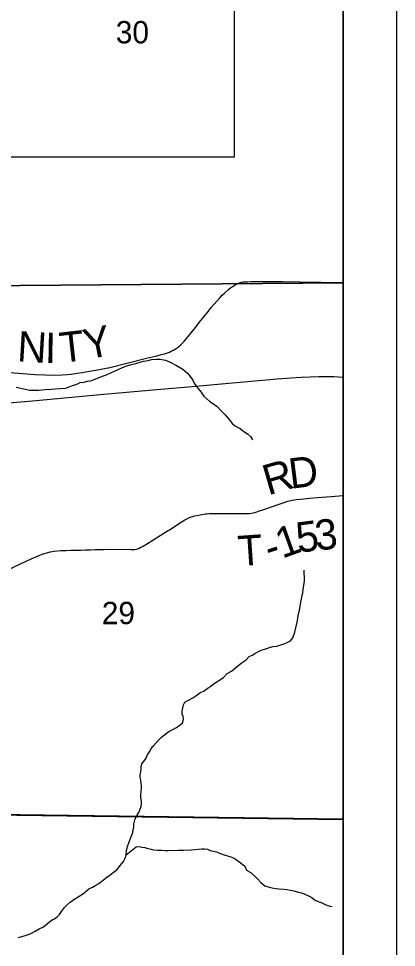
# Model space of a CAD drawing. Extents: x 0 to 34, y 0 to 22.
# Drawn here: x 16.791 to 17.5, y 16.673 to 18.414 of the extents above; entities that cross this region are included whole.
import ezdxf

# ---------------------------------------------------------------- set-up
doc = ezdxf.new("R2010")
doc.units = 0
for name, color, linetype in [('GM_X_Corporation', 7, 'Continuous'), ('GM_X_Minor_River', 7, 'Continuous'), ('GM_X_Rail_Line', 7, 'Continuous'), ('GM_X_Section_Text', 7, 'Continuous'), ('GM_X_Township_Road', 7, 'Continuous'), ('GM_X_Township_Road_Text', 7, 'Continuous'), ('SH_Data', 7, 'Continuous'), ('SH_Text', 7, 'Continuous')]:
    doc.layers.add(name, color=color, linetype=linetype)

msp = doc.modelspace()

# ---------------------------------------------------------------- linework, layer by layer
at = {"layer": 'GM_X_Corporation'}
for points in [[(17.4, 16.913), (17.4, 20.4), (16.7661, 20.4), (16.7652, 20.328), (16.7547, 19.2837), (16.7532, 19.0614), (16.752, 18.8891), (16.5475, 18.8929), (16.5174, 18.8935), (16.5168, 18.8707), (16.4886, 17.7392), (16.4807, 17.4161), (16.4704, 17.0104), (16.4703, 17.0036), (16.4689, 16.9245), (16.5516, 16.9243)], [(17.4, 17.9189), (17.4, 18.8808), (16.7485, 18.8896), (16.5138, 18.8938), (16.4906, 17.9114)], [(17.4, 16.9134), (17.4, 17.9189), (16.4906, 17.9114), (16.466, 16.9263)], [(16.4214, 13.6), (17.4, 13.6), (17.4, 16.913), (16.5516, 16.9243), (16.4689, 16.9245), (16.4603, 16.2617), (16.4611, 16.1288), (16.4516, 15.5964), (16.4498, 15.4626), (16.4419, 14.8642), (16.438, 14.5908), (16.4339, 14.3806), (16.4212, 13.6609)], [(17.4, 15.8967), (17.4, 16.9134), (16.466, 16.9263), (16.466, 16.9214), (16.4563, 15.9084)]]:
    msp.add_lwpolyline(points, close=True, dxfattribs=at)
at = {"layer": 'GM_X_Minor_River'}
for points in [[(16.7866, 17.7233), (16.7923, 17.7223), (16.8037, 17.7198), (16.8124, 17.7181), (16.8189, 17.7178), (16.8287, 17.718), (16.8412, 17.719), (16.853, 17.7199), (16.8601, 17.7204), (16.8692, 17.721), (16.8791, 17.7215), (16.8859, 17.7239), (16.8923, 17.7267), (16.899, 17.7287), (16.9066, 17.7319), (16.9141, 17.7328), (16.9198, 17.7344), (16.9258, 17.7352), (16.9349, 17.7384), (16.9405, 17.7412), (16.9507, 17.7448), (16.9571, 17.7472), (16.9654, 17.7511), (16.9778, 17.7563), (16.9864, 17.7602), (16.9944, 17.7634), (17.0008, 17.7654), (17.011, 17.7679), (17.0193, 17.7703), (17.0257, 17.7719), (17.034, 17.7736), (17.0408, 17.7752), (17.0502, 17.7761), (17.0567, 17.7759), (17.0666, 17.7741), (17.0753, 17.7701), (17.0872, 17.7639), (17.0991, 17.7572), (17.1083, 17.7494), (17.1129, 17.7434), (17.118, 17.7367), (17.1204, 17.731), (17.127, 17.722), (17.1335, 17.7138), (17.139, 17.7066), (17.1501, 17.6969), (17.1567, 17.6921), (17.1639, 17.6873), (17.1713, 17.6791), (17.1782, 17.6724), (17.186, 17.6626), (17.1921, 17.6555), (17.1983, 17.6503), (17.2067, 17.6459), (17.214, 17.6403), (17.2205, 17.6359), (17.2263, 17.631), (17.2302, 17.6246)], [(17.1988, 17.1979), (17.2089, 17.206), (17.2179, 17.2126), (17.2235, 17.2184), (17.2291, 17.2208), (17.2343, 17.2243), (17.2411, 17.2282), (17.246, 17.2302), (17.2509, 17.2318), (17.2566, 17.2334), (17.2618, 17.2354), (17.269, 17.2371), (17.2754, 17.2379), (17.2834, 17.2403), (17.2894, 17.2423), (17.295, 17.2451), (17.3014, 17.2479), (17.3059, 17.2533), (17.3095, 17.2643), (17.3112, 17.2724), (17.3137, 17.283), (17.3151, 17.2907), (17.3165, 17.2987), (17.3183, 17.3051), (17.3196, 17.3131), (17.3207, 17.3204), (17.3221, 17.3261), (17.3227, 17.331), (17.3242, 17.3375), (17.3248, 17.3451), (17.3269, 17.3554), (17.3275, 17.3608), (17.3272, 17.3805)], [(16.7905, 16.6917), (16.7999, 16.6945), (16.8078, 16.6969), (16.8157, 16.7001), (16.8225, 16.7036), (16.83, 16.7079), (16.8364, 16.7115), (16.8412, 16.7142), (16.8461, 16.7188), (16.854, 16.7247), (16.8585, 16.7266), (16.8633, 16.7305), (16.8682, 16.7352), (16.8715, 16.7409), (16.8771, 16.7479), (16.8823, 16.7533), (16.8879, 16.7583), (16.895, 16.763), (16.9029, 16.7681), (16.91, 16.7727), (16.9145, 16.7755), (16.9227, 16.7832), (16.9299, 16.786), (16.9362, 16.7899), (16.9419, 16.7934), (16.9501, 16.7993), (16.9572, 16.8055), (16.9624, 16.809), (16.9688, 16.8136), (16.9759, 16.8195), (16.9822, 16.8272), (16.9878, 16.8345), (16.9918, 16.8418), (16.9929, 16.8471), (16.9939, 16.8543), (16.9956, 16.8624), (16.9985, 16.8715), (17.0029, 16.8822), (17.0054, 16.8887), (17.0061, 16.8941), (17.0072, 16.8986), (17.0074, 16.9043), (17.0099, 16.9143), (17.0136, 16.9215), (17.0177, 16.9277), (17.0195, 16.9323), (17.0209, 16.9376), (17.0216, 16.943), (17.0215, 16.9475), (17.0206, 16.954), (17.0205, 16.9589), (17.0212, 16.9661), (17.0215, 16.9711), (17.0218, 16.9764), (17.0213, 16.9809), (17.0204, 16.9866), (17.0192, 16.9915), (17.0191, 16.9972), (17.0205, 17.0026), (17.0212, 17.0071), (17.0212, 17.0117), (17.0226, 17.0174), (17.0274, 17.0236), (17.0307, 17.0282), (17.0333, 17.0351), (17.0377, 17.0405), (17.0399, 17.0462), (17.0436, 17.0508), (17.0488, 17.0559), (17.0537, 17.062), (17.0589, 17.0667), (17.0656, 17.0725), (17.0731, 17.0783), (17.0817, 17.0826), (17.0877, 17.0858), (17.0945, 17.0905), (17.099, 17.094), (17.1004, 17.1004), (17.0999, 17.1061), (17.0979, 17.1107), (17.0982, 17.1164), (17.1003, 17.1278), (17.1029, 17.1328), (17.1089, 17.1363), (17.1179, 17.141), (17.1239, 17.1449), (17.1314, 17.1504), (17.1393, 17.1543), (17.1468, 17.1597), (17.1513, 17.1625), (17.1565, 17.1667), (17.1756, 17.1792), (17.1823, 17.1866), (17.1906, 17.1909), (17.1988, 17.1979)], [(16.9929, 16.8471), (17.0116, 16.8619), (17.0176, 16.8624), (17.0226, 16.8613), (17.0279, 16.8603), (17.0336, 16.8588), (17.0397, 16.8574), (17.0446, 16.8564), (17.0515, 16.8557), (17.0598, 16.8555), (17.0659, 16.8552), (17.0716, 16.8549), (17.0905, 16.8553), (17.1011, 16.8558), (17.1155, 16.8564), (17.1288, 16.8574), (17.1348, 16.8579), (17.1401, 16.858), (17.1454, 16.8573), (17.1504, 16.8548), (17.1622, 16.8523), (17.1679, 16.8501), (17.1786, 16.8465), (17.1832, 16.8451), (17.1912, 16.8422), (17.1977, 16.8392), (17.2042, 16.8344), (17.2096, 16.8303), (17.2157, 16.8255), (17.2189, 16.8179), (17.2273, 16.8132), (17.2385, 16.8023), (17.2458, 16.7949), (17.2531, 16.7885), (17.2638, 16.7853), (17.2699, 16.7843), (17.2744, 16.7836), (17.2797, 16.7829), (17.2885, 16.7823), (17.2949, 16.7816), (17.3006, 16.7806), (17.3098, 16.7785), (17.3159, 16.7767), (17.322, 16.7753), (17.3269, 16.7735), (17.3365, 16.7691), (17.341, 16.7669), (17.3464, 16.7628), (17.3529, 16.7595), (17.3586, 16.7573), (17.3678, 16.7529), (17.3731, 16.7514), (17.3796, 16.7497)]]:
    msp.add_lwpolyline(points, dxfattribs=at)
at = {"layer": 'GM_X_Rail_Line'}
msp.add_lwpolyline([(16.7367, 17.6911), (16.8171, 17.6981), (16.9511, 17.7102), (17.0363, 17.7176), (17.1166, 17.7247), (17.1652, 17.7291), (17.2765, 17.7389), (17.3024, 17.741), (17.3212, 17.7422), (17.3382, 17.7431), (17.3543, 17.7435), (17.3682, 17.7436), (17.3828, 17.7432), (17.3993, 17.7425), (17.4, 17.7425)], dxfattribs=at)
at = {"layer": 'GM_X_Township_Road'}
for points in [[(16.7753, 17.7508), (16.7918, 17.7496), (16.8218, 17.7474), (16.8405, 17.7466), (16.8568, 17.7462), (16.873, 17.7465), (16.8822, 17.747), (16.8899, 17.7478), (16.9013, 17.7495), (16.9105, 17.7508), (16.9242, 17.7532), (16.943, 17.7565), (16.9526, 17.7584), (16.9623, 17.7606), (16.9941, 17.7683), (17.0313, 17.7778), (17.048, 17.7817), (17.0594, 17.7844), (17.065, 17.7859), (17.0703, 17.7877), (17.0744, 17.7893), (17.0776, 17.7907), (17.0818, 17.7929), (17.0851, 17.7949), (17.0887, 17.7972), (17.0917, 17.7997), (17.0961, 17.8036), (17.1025, 17.8102), (17.1062, 17.8145), (17.1096, 17.8184), (17.1129, 17.8225), (17.118, 17.8293), (17.1228, 17.8352), (17.1302, 17.8445), (17.1395, 17.856), (17.1476, 17.8662), (17.1523, 17.8725), (17.1575, 17.8785), (17.1691, 17.8913), (17.1732, 17.8957), (17.1777, 17.8998), (17.1842, 17.9056), (17.1893, 17.9101), (17.1918, 17.9118), (17.1945, 17.9136), (17.1975, 17.9154), (17.2007, 17.9171), (17.2049, 17.9189), (17.2092, 17.9201), (17.2124, 17.9206), (17.2164, 17.921), (17.2214, 17.9212), (17.2273, 17.9214), (17.236, 17.9215), (17.2486, 17.9217), (17.2862, 17.9215), (17.3189, 17.921), (17.3579, 17.92), (17.3783, 17.9197), (17.3929, 17.9198), (17.4, 17.9198)], [(16.7712, 17.3809), (16.7949, 17.3922), (16.8146, 17.4016), (16.827, 17.4069), (16.8388, 17.4115), (16.8439, 17.4131), (16.8506, 17.4147), (16.8585, 17.416), (16.8702, 17.417), (16.8802, 17.4175), (16.8888, 17.4177), (16.8965, 17.4179), (16.9078, 17.4181), (16.9167, 17.4184), (16.9263, 17.4186), (16.9348, 17.4189), (16.9416, 17.4191), (16.951, 17.4193), (16.9595, 17.4195), (17.0027, 17.4189), (17.0064, 17.4191), (17.0093, 17.4194), (17.0117, 17.4198), (17.0146, 17.4207), (17.0176, 17.4219), (17.0203, 17.4233), (17.0249, 17.4256), (17.0331, 17.4302), (17.0686, 17.4527), (17.0759, 17.4574), (17.0978, 17.4719), (17.1032, 17.4749), (17.1093, 17.4782), (17.1149, 17.4802), (17.1217, 17.482), (17.1289, 17.4835), (17.1351, 17.4848), (17.1419, 17.4859), (17.1452, 17.4863), (17.1493, 17.4866), (17.1562, 17.4869), (17.1644, 17.4868), (17.1816, 17.4866), (17.2184, 17.4864), (17.2238, 17.4865), (17.2288, 17.4871), (17.236, 17.489), (17.2434, 17.4914), (17.2513, 17.4941), (17.2678, 17.4998), (17.2765, 17.503), (17.2876, 17.5068), (17.2965, 17.5096), (17.3043, 17.5115), (17.312, 17.5126), (17.3202, 17.5135), (17.3376, 17.5152), (17.3521, 17.5167), (17.3773, 17.5187), (17.3998, 17.5207), (17.4, 17.5207)]]:
    msp.add_lwpolyline(points, dxfattribs=at)
at = {"layer": 'SH_Data'}
for points in [[(10.5, 20.5), (17.5, 20.5), (17.5, 13.5), (10.5, 13.5)], [(10.6, 20.4), (17.4, 20.4), (17.4, 13.6), (10.6, 13.6)]]:
    msp.add_lwpolyline(points, close=True, dxfattribs=at)
at = {"layer": 'SH_Text'}
msp.add_lwpolyline([(15.4984, 18.8798), (17.1957, 18.8798), (17.1957, 18.1549), (15.4984, 18.1549)], close=True, dxfattribs=at)

# ---------------------------------------------------------------- texts
at = {"layer": 'GM_X_Section_Text'}
for s, p in [('30', (16.9736, 18.3679)), ('29', (16.9473, 17.2792))]:
    msp.add_text(s, height=0.04186, rotation=0, dxfattribs=at).set_placement(p)
at = {"layer": 'GM_X_Township_Road_Text'}
for s, rotation, p in [('T', 6.4293, (16.8714, 17.7689)), ('Y', 11.7177, (16.9192, 17.7746)), ('N', 356.5191, (16.7876, 17.7721)), ('I', 358.9082, (16.8401, 17.769)), ('R', 16.2869, (17.2591, 17.5203)), ('D', 7.0776, (17.3015, 17.5329)), ('1', 19.6752, (17.2855, 17.4018)), ('5', 7.3471, (17.3153, 17.4128)), ('3', 5.5563, (17.3496, 17.4172)), ('T', 3.8255, (17.2043, 17.3879)), ('-', 18.8901, (17.2626, 17.3939))]:
    msp.add_text(s, height=0.0568, rotation=rotation, dxfattribs=at).set_placement(p)

doc.saveas('drawing.dxf')
